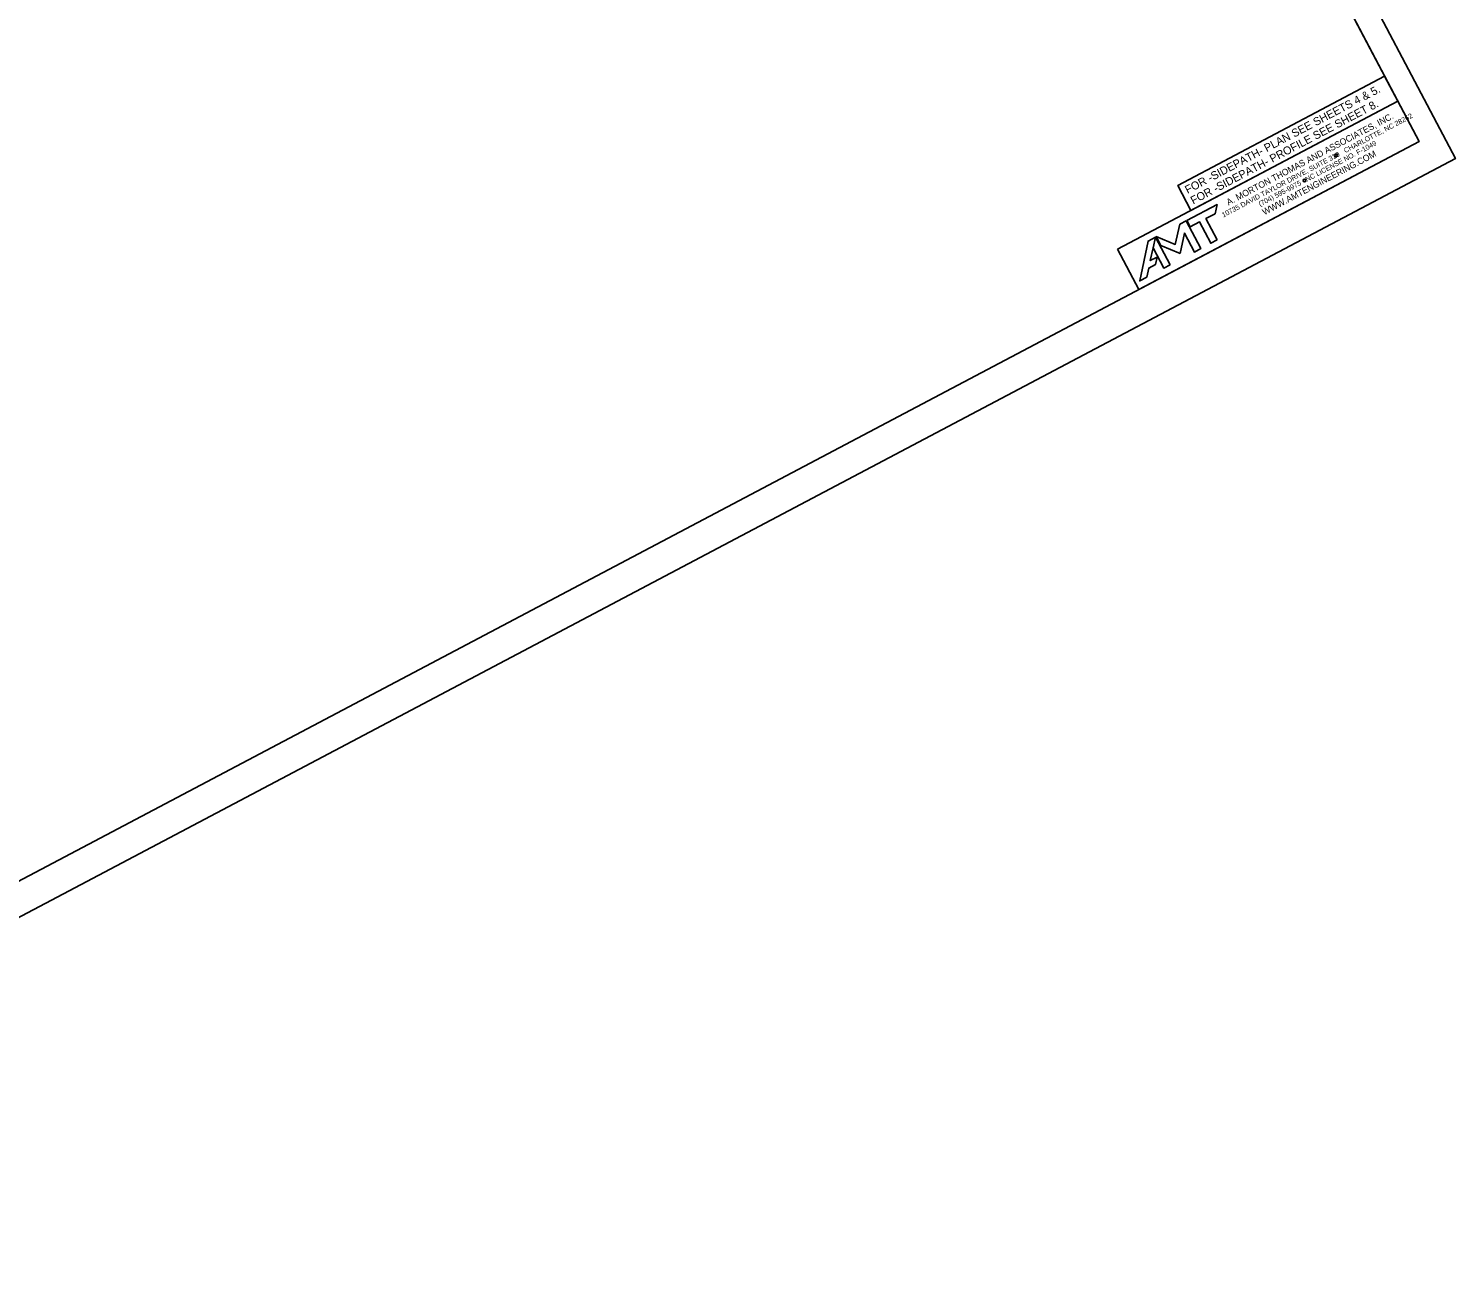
# Model space of a CAD drawing. Extents: x 1487051 to 1489051, y 497582 to 499336.
# Drawn here: x 1488051 to 1489051, y 497582 to 498459 of the extents above; entities that cross this region are included whole.
import ezdxf

# ---------------------------------------------------------------- set-up
doc = ezdxf.new("R2010")
doc.units = 0
for name, color, linetype in [('Prop Grid Mask', 7, 'Continuous'), ('Prop Horizontal Alignment Curve and Spiral Data', 7, 'Continuous'), ('Sheet Block Title CELL', 7, 'Continuous'), ('Sheet Clip Boundary CELL', 7, 'Continuous'), ('Sheet Plan CELL', 7, 'Continuous'), ('Sheet Plot Border Outside CELL', 7, 'Continuous')]:
    doc.layers.add(name, color=color, linetype=linetype)

msp = doc.modelspace()

# ---------------------------------------------------------------- linework, layer by layer
at = {"layer": 'Prop Grid Mask'}
for points in [[(1488865.49, 498331.71), (1489010.47, 498408.26), (1489001.26, 498425.69), (1488856.29, 498349.14)], [(1488814.13, 498304.59), (1489010.48, 498408.27), (1489025.4, 498380.01), (1488829.05, 498276.33)]]:
    msp.add_lwpolyline(points, close=True, dxfattribs=at)
at = {"layer": 'Sheet Block Title CELL'}
msp.add_lwpolyline([(1488814.13, 498304.59), (1489010.48, 498408.27), (1489025.4, 498380.01), (1488829.05, 498276.33)], close=True, dxfattribs=at)
for points in [[(1488883.93, 498311.01), (1488876.03, 498325.97), (1488882.48, 498329.38), (1488883.85, 498335.8), (1488862.72, 498324.64), (1488865.08, 498320.19), (1488871.58, 498323.62), (1488879.48, 498308.66), (1488883.93, 498311.01)], [(1488857.9, 498301.64), (1488860.96, 498315.83), (1488867.95, 498302.58), (1488872.41, 498304.93), (1488862.16, 498324.34), (1488857.7, 498321.99), (1488854.57, 498307.95), (1488841.3, 498313.33), (1488844.56, 498307.15), (1488857.9, 498301.64)], [(1488839.03, 498305.46), (1488840.73, 498313.03), (1488835.53, 498310.28), (1488829.66, 498282.36), (1488834.7, 498285.02), (1488836.01, 498291.29), (1488840.63, 498293.73), (1488841.86, 498299.07), (1488837.08, 498296.55), (1488839.03, 498305.46)], [(1488850.98, 498293.61), (1488840.73, 498313.03), (1488839.03, 498305.46), (1488846.53, 498291.26), (1488850.98, 498293.61)]]:
    msp.add_lwpolyline(points, dxfattribs=at)
for centre in [(1488967.39, 498370.33), (1488945.15, 498352.67)]:
    msp.add_circle(centre, 1, dxfattribs=at)
at = {"layer": 'Sheet Clip Boundary CELL'}
msp.add_lwpolyline([(1487208.66, 498608.09), (1488223.53, 499144), (1488876.96, 498661.12), (1489025.39, 498380), (1487698.94, 497679.61)], close=True, dxfattribs=at)
at = {"layer": 'Sheet Plan CELL'}
for points in [[(1488535.14, 499308.53), (1487208.67, 498608.12), (1487698.94, 497679.61), (1489025.4, 498380.01)], [(1487698.94, 497679.61), (1487208.66, 498608.09), (1488358.21, 499215.12), (1488428.29, 499082.43), (1488605.19, 499175.82), (1489025.4, 498380.01)]]:
    msp.add_lwpolyline(points, close=True, dxfattribs=at)
at = {"layer": 'Sheet Plot Border Outside CELL'}
msp.add_lwpolyline([(1487562.23, 497581.96), (1489050.94, 498368.04), (1488539.66, 499336.34), (1487050.94, 498550.27)], close=True, dxfattribs=at)

# ---------------------------------------------------------------- texts
at = {"layer": 'Prop Horizontal Alignment Curve and Spiral Data'}
for s, p in [('FOR -SIDEPATH- PLAN SEE SHEETS 4 & 5.', (1488863.21, 498343.24)), ('FOR -SIDEPATH- PROFILE SEE SHEET 8.', (1488867.15, 498335.78))]:
    msp.add_text(s, height=5.625, rotation=27.83509, dxfattribs=at).set_placement(p)
at = {"layer": 'Sheet Block Title CELL'}
for s, height, p in [('10735 DAVID TAYLOR DRIVE, SUITE 310   CHARLOTTE, NC 28262', 3.5, (1488888.31, 498326.68)), ('A. MORTON THOMAS AND ASSOCIATES, INC.', 4.5, (1488891.9, 498335.08)), ('(704) 595-9975   NC LICENSE NO. F-1049', 3.5, (1488914.09, 498334.36)), ('WWW.AMTENGINEERING.COM', 4.5, (1488917.01, 498328.27))]:
    msp.add_text(s, height=height, rotation=27.83461, dxfattribs=at).set_placement(p)

doc.saveas('drawing.dxf')
